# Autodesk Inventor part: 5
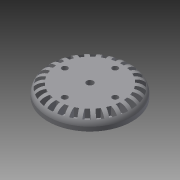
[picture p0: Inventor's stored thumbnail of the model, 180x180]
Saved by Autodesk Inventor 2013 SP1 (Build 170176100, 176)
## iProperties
Created: 2013-05
Part Number: 5
Material: Steel, High Strength Low Alloy
Document SubType Name: Modeling
Designer: 50384
Density: 1 g/cm^3
Author: 50384
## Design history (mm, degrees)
sketch "Sketch1"
  geometry: L1 (3.565, 47.366)-(2.165, 37.938); L2 (-3.565, 47.366)-(-2.165, 37.938); L3 (-7.874, 46.843)-(-6.977, 37.354); L4 (-14.797, 45.136)-(-11.181, 36.318); L5 (-18.855, 43.597)-(-15.714, 34.599); L6 (-25.169, 40.284)-(-19.548, 32.587); L7 (-28.741, 37.818)-(-23.537, 29.833); L8 (-34.078, 33.09)-(-26.778, 26.962); L9 (-36.956, 29.841)-(-29.993, 23.333); L10 (-41.007, 23.973)-(-32.452, 19.77); L11 (-43.024, 20.13)-(-34.705, 15.477); L12 (-45.552, 13.463)-(-36.241, 11.429); L13 (-46.591, 9.248)-(-37.401, 6.722); L14 (-47.45, 2.17)-(-37.923, 2.424); L15 (-47.45, -2.17)-(-37.923, -2.424); L16 (-46.591, -9.248)-(-37.401, -6.722); L17 (-45.552, -13.463)-(-36.241, -11.429); L18 (-43.024, -20.13)-(-34.705, -15.477); L19 (-41.007, -23.973)-(-32.452, -19.77); L20 (-36.956, -29.841)-(-29.993, -23.333); L21 (-34.078, -33.09)-(-26.778, -26.962); L22 (-28.741, -37.818)-(-23.537, -29.833); L23 (-25.169, -40.284)-(-19.548, -32.587); L24 (-18.855, -43.597)-(-15.714, -34.599); L25 (-14.797, -45.136)-(-11.181, -36.318); L26 (-7.874, -46.843)-(-6.977, -37.354); L27 (-3.565, -47.366)-(-2.165, -37.938); L28 (3.565, -47.366)-(2.165, -37.938); L29 (7.874, -46.843)-(6.977, -37.354); L30 (14.797, -45.136)-(11.181, -36.318); L31 (18.855, -43.597)-(15.714, -34.599); L32 (25.169, -40.284)-(19.548, -32.587); L33 (28.741, -37.818)-(23.537, -29.833); L34 (34.078, -33.09)-(26.778, -26.962); L35 (36.956, -29.841)-(29.993, -23.333); L36 (41.007, -23.973)-(32.452, -19.77); L37 (43.024, -20.13)-(34.705, -15.477); L38 (45.552, -13.463)-(36.241, -11.429); L39 (46.591, -9.248)-(37.401, -6.722); L40 (47.45, -2.17)-(37.923, -2.424); L41 (47.45, 2.17)-(37.923, 2.424); L42 (46.591, 9.248)-(37.401, 6.722); L43 (45.552, 13.463)-(36.241, 11.429); L44 (43.024, 20.13)-(34.705, 15.477); L45 (41.007, 23.973)-(32.452, 19.77); L46 (36.956, 29.841)-(29.993, 23.333); L47 (34.078, 33.09)-(26.778, 26.962); L48 (28.741, 37.818)-(23.537, 29.833); L49 (25.169, 40.284)-(19.548, 32.587); L50 (18.855, 43.597)-(15.714, 34.599); L51 (14.797, 45.136)-(11.181, 36.318); L52 (7.874, 46.843)-(6.977, 37.354); C1 r 50 at (0, 0); C2 r 3.4 at (0, 30); C3 r 3.4 at (-30, 0); C4 r 3.4 at (0, -30); C5 r 3.4 at (30, 0); A1 r 47.5 centre (0, 0) between (3.565, 47.366) and (-3.565, 47.366); A2 r 38 centre (0, 0) between (2.165, 37.938) and (-2.165, 37.938); A3 r 47.5 centre (0, 0) between (-7.874, 46.843) and (-14.797, 45.136); A4 r 38 centre (0, 0) between (-6.977, 37.354) and (-11.181, 36.318); A5 r 47.5 centre (0, 0) between (-18.855, 43.597) and (-25.169, 40.284); A6 r 38 centre (0, 0) between (-15.714, 34.599) and (-19.548, 32.587); A7 r 47.5 centre (0, 0) between (-28.741, 37.818) and (-34.078, 33.09); A8 r 38 centre (0, 0) between (-23.537, 29.833) and (-26.778, 26.962); A9 r 47.5 centre (0, 0) between (-36.956, 29.841) and (-41.007, 23.973); A10 r 38 centre (0, 0) between (-29.993, 23.333) and (-32.452, 19.77); A11 r 47.5 centre (0, 0) between (-43.024, 20.13) and (-45.552, 13.463); A12 r 38 centre (0, 0) between (-34.705, 15.477) and (-36.241, 11.429); A13 r 47.5 centre (0, 0) between (-46.591, 9.248) and (-47.45, 2.17); A14 r 38 centre (0, 0) between (-37.401, 6.722) and (-37.923, 2.424); A15 r 47.5 centre (0, 0) between (-47.45, -2.17) and (-46.591, -9.248); A16 r 38 centre (0, 0) between (-37.923, -2.424) and (-37.401, -6.722); A17 r 47.5 centre (0, 0) between (-45.552, -13.463) and (-43.024, -20.13); A18 r 38 centre (0, 0) between (-36.241, -11.429) and (-34.705, -15.477); A19 r 47.5 centre (0, 0) between (-41.007, -23.973) and (-36.956, -29.841); A20 r 38 centre (0, 0) between (-32.452, -19.77) and (-29.993, -23.333); A21 r 47.5 centre (0, 0) between (-34.078, -33.09) and (-28.741, -37.818); A22 r 38 centre (0, 0) between (-26.778, -26.962) and (-23.537, -29.833); A23 r 47.5 centre (0, 0) between (-25.169, -40.284) and (-18.855, -43.597); A24 r 38 centre (0, 0) between (-19.548, -32.587) and (-15.714, -34.599); A25 r 47.5 centre (0, 0) between (-14.797, -45.136) and (-7.874, -46.843); A26 r 38 centre (0, 0) between (-11.181, -36.318) and (-6.977, -37.354); A27 r 47.5 centre (0, 0) between (-3.565, -47.366) and (3.565, -47.366); A28 r 38 centre (0, 0) between (-2.165, -37.938) and (2.165, -37.938); A29 r 47.5 centre (0, 0) between (7.874, -46.843) and (14.797, -45.136); A30 r 38 centre (0, 0) between (6.977, -37.354) and (11.181, -36.318); A31 r 47.5 centre (0, 0) between (18.855, -43.597) and (25.169, -40.284); A32 r 38 centre (0, 0) between (15.714, -34.599) and (19.548, -32.587); A33 r 47.5 centre (0, 0) between (28.741, -37.818) and (34.078, -33.09); A34 r 38 centre (0, 0) between (23.537, -29.833) and (26.778, -26.962); A35 r 47.5 centre (0, 0) between (36.956, -29.841) and (41.007, -23.973); A36 r 38 centre (0, 0) between (29.993, -23.333) and (32.452, -19.77); A37 r 47.5 centre (0, 0) between (43.024, -20.13) and (45.552, -13.463); A38 r 38 centre (0, 0) between (34.705, -15.477) and (36.241, -11.429); A39 r 47.5 centre (0, 0) between (46.591, -9.248) and (47.45, -2.17); A40 r 38 centre (0, 0) between (37.401, -6.722) and (37.923, -2.424); A41 r 47.5 centre (0, 0) between (47.45, 2.17) and (46.591, 9.248); A42 r 38 centre (0, 0) between (37.923, 2.424) and (37.401, 6.722); A43 r 47.5 centre (0, 0) between (45.552, 13.463) and (43.024, 20.13); A44 r 38 centre (0, 0) between (36.241, 11.429) and (34.705, 15.477); A45 r 47.5 centre (0, 0) between (41.007, 23.973) and (36.956, 29.841); A46 r 38 centre (0, 0) between (32.452, 19.77) and (29.993, 23.333); A47 r 47.5 centre (0, 0) between (34.078, 33.09) and (28.741, 37.818); A48 r 38 centre (0, 0) between (26.778, 26.962) and (23.537, 29.833); A49 r 47.5 centre (0, 0) between (25.169, 40.284) and (18.855, 43.597); A50 r 38 centre (0, 0) between (19.548, 32.587) and (15.714, 34.599); A51 r 47.5 centre (0, 0) between (14.797, 45.136) and (7.874, 46.843); A52 r 38 centre (0, 0) between (11.181, 36.318) and (6.977, 37.354)
  constraints: 104 end point, 104 point on circle, 57 centre point, 27 coincident, 270 other
  dimensions: "d10" = 360 deg dimension on C1.centre L1.start (derived); "d13" = 6.8 diameter of C2; "d16" = 360 deg dimension on C1.centre C2.centre (derived)
extrude "Extrusion1" new body sketch "Sketch1" distance "d18" = 10; taper "d19" = 0 deg
fillet "Fillet1" dims "d20" = 12
sketch "Sketch2"
  geometry: C1 r 50 at (0, 0) reference
extrude "Extrusion2" join sketch "Sketch2" distance "d21" = 5; taper "d22" = 0 deg
sketch "Sketch3"
  geometry: C1 r 4 at (0, 0); A1 r 38 centre (0, 0) between (2.165, 37.938) and (-2.165, 37.938) reference
  constraints: 1 centre point, 1 coincident
  dimensions: "d23" = 8 diameter of C1
extrude "Extrusion3" cut sketch "Sketch3" stored distance "d24" = 5; taper "d25" = 0 deg
body "Solid1"
